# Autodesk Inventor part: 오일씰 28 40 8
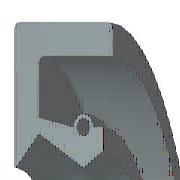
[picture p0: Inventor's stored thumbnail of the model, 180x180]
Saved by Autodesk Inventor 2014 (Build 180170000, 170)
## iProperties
IsCustomPart: 1
Created: 2012-02
Part Number: 오일씰 28 40 8
Material: 고무
Description: Oil-seal
Document SubType Name: Modeling
Standard: KS B 2804
Designer: mduedu
Standards Organization: KS
Language: en-US
Size Designation: D - 28 40 8
Categories: <MemberInstance><Categories><Category DisplayName="Shaft Parts" InternalName="7f7aeb1f-a693-4053-b835-cee3144e0d98" Mnemonic="SHFT"><Category DisplayName="Seali
Density: 0.93 g/cm^3
Mass: 2.83894 g
Surface Area: 40.7521 cm^2
Volume: 3.05262 cm^3
Appearance: 고무 - 검은색 - 버전 1.1
Author: mduedu
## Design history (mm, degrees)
sketch "Sketch1"
  geometry: L1 (0, 20)-(8, 20); L2 (8, 18.25)-(1.75, 18.25); L3 (1.75, 15.75)-(4.9, 14); L4 (4.9, 14)-(0, 14); L5 (0, 0)-(9.586, 0) reference; L6 (4.9, 14)-(6.3, 14.875); L7 (0, 18)-(0, -3) reference; L8 (-1.941, 0)-(11.507, 0) reference; L9 (4.2, 16.1)-(1.75, 16.71); L10 (1.75, 16.71)-(1.75, 18.25); L11 (0, 20)-(0, 14.088); L12 (4.9, 14)-(0, 14); L13 (1.75, 15.75)-(0.152, 14.028); L14 (8, 20)-(8, 18.25); L15 (5.6, 16.1)-(6.3, 16.1); L16 (6.3, 16.1)-(6.3, 14.875); C1 r 0.455 at (4.9, 16.1); A1 r 0.7 centre (4.9, 16.1) between (5.6, 16.1) and (4.2, 16.1); A2 r 0.088 centre (0.087, 14.088) between (0, 14.088) and (0.152, 14.028); 1 further point
  constraints: 28 end point, 5 horizontal alignment, 5 point on line, 4 point on circle, 4 vertical alignment, 3 centre point, 3 tangent, 2 collinear, 2 horizontal, 2 perpendicular, 1 coincident, 1 parallel
  dimensions: "d0" = 40 diameter of L1 L5 (= SD2); "d1" = 1.75 distance of L1.end L2.start (= SD); "d2" = 0.91 diameter of C1 (= SPDI); "d3" = 1.4 diameter of A1 (= SPDA); "d4" = 28 diameter of L3.end L5 (= NND); "d5" = 31.5 diameter of L3.start L5 (= TKDM); "d7" = 33.42 diameter of L9.end L5 (= TKDM + 0.24 x SWDT); "d8" = 1.75 distance between parallel lines of L11 L10 (= SD); "d9" = 4.9 distance from line of L11 C1.centre (= SPDST); "d10" = 32.2 diameter of C1.centre L5 (= HLDM); "d11" = 0.0875 radius of A2 (= 0.25 x LAB); "d12" = 6.3 distance between parallel lines of L11 L16 (= SDI); "d13" = 29.75 diameter of L6.end L5 (= ABDM); "d14" = 8 distance from line of L11 L1.end (= SWDT)
revolve "Body" stored, may be unused: angle "d17" = 90 deg
revolve "Spring1" stored, may be unused: angle "d18" = 90 deg
fillet "Fillet1" dims "d6" = 0.4 (= RR)
body "Solid1"
other parameters: "SD2" = 40 [user parameter; used in 1 equation term], "SWDT" = 8 [user parameter; used in 2 equation terms], "RR" = 0.4 [user parameter; used in 1 equation term], "SD" = 1.75 [user parameter; used in 2 equation terms], "NND" = 28 [user parameter; used in 1 equation term], "SPDA" = 1.4 [user parameter; used in 1 equation term], "SPDI" = 0.91 [user parameter; used in 1 equation term], "TKDM" = 31.5 [user parameter; used in 2 equation terms], "HLDM" = 32.2 [user parameter; used in 1 equation term], "ABDM" = 29.75 [user parameter; used in 1 equation term], "SDI" = 6.3 [user parameter; used in 1 equation term], "SPDST" = 4.9 [user parameter; used in 1 equation term], "LAB" = 0.35 [user parameter; used in 1 equation term], "d15" = 0, "d16" = 0, "d19" = 0
